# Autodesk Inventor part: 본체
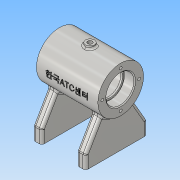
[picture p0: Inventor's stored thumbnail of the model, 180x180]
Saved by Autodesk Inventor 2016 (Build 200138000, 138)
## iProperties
Created: 2018-05
Part Number: 본체
Material: 알루미늄 6061
Document SubType Name: Modeling
Designer: Administrator
Density: 2.7 g/cm^3
Appearance: 알루미늄 - 평지
Author: Administrator
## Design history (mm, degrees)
sketch "스케치1"
  geometry: L1 (-30, 35)-(30, 35); L2 (30, 35)-(30, -35); L3 (30, -35)-(-30, -35); L4 (-30, -35)-(-30, 35); L5 (-20, 35)-(-20, -35); L6 (20, 35)-(20, -35); 3 further points
  constraints: 12 end point, 4 point on line, 3 perpendicular, 2 midpoint, 2 parallel, 1 horizontal, 1 horizontal alignment, 1 vertical alignment
  dimensions: "d0" = 60 distance of L2.end L3.end; "d1" = 70 distance of L1.end L2.end; "d2" = 10 distance between parallel lines of L5 L4; "d3" = 10 distance between parallel lines of L2 L6
extrude "돌출1" new body sketch "스케치1" distance "d4" = 15; taper "d5" = 0 deg
sketch "스케치2"
  geometry: L1 (35, 65)-(-35, 65); L2 (35, 65)-(35, 91); L3 (35, 91)-(-35, 91); L4 (-35, 91)-(-35, 65); 2 further points
  constraints: 8 end point, 2 perpendicular, 1 horizontal, 1 midpoint, 1 vertical, 1 vertical alignment
  dimensions: "d7" = 65 distance from line of point (0, 0) L1; "d8" = 70 distance of L1.start L1.end; "d9" = 52 diameter of L3 L1
revolve "회전1" sketch "스케치2" stored, may be unused: angle "d10" = 90 deg
sketch "스케치3"
  geometry: L1 (0, 0)-(-15, 0) reference; L2 (-15, 0)-(-45.614, 17.675); L3 (0, 70)-(-15, 70) reference; L4 (-15, 70)-(-45.614, 52.325); L5 (-15, 0)-(-15, 70) reference; A1 r 26 centre (-65, 35) between (-45.614, 17.675) and (-45.614, 52.325) reference; 1 further point
  constraints: 4 end point, 2 point on circle
  dimensions: "d11" = 30 deg angle of L2 L1; "d12" = 30 deg angle of L4 L3
extrude "돌출2" join sketch "스케치3" distance "d13" = 10; taper "d14" = 0 deg
sketch "스케치4"
  geometry: L1 (0, 0)-(0, 119.378); L2 (0, 65)-(35.22, -31.765); L3 (9.919, 37.749)-(15.557, 39.801); L4 (15.557, 39.801)-(14.291, 43.28); L5 (14.291, 43.28)-(8.653, 41.227); L6 (8.653, 41.227)-(9.919, 37.749)
  constraints: 12 end point, 3 perpendicular, 2 point on line, 1 vertical, 2 other
  dimensions: "d15" = 20 deg angle of L2 L1; "d16" = 6 distance of L3.start L3.end; "d17" = 29 distance from line of L3 L2.start
revolve "회전2" sketch "스케치4" stored, may be unused: angle "d18" = 90 deg
sketch "스케치5"
  geometry: L1 (0, 94)-(5, 94); L2 (5, 94)-(5, 90.515); L3 (5, 90.515)-(0, 90.515); L4 (0, 90.515)-(0, 94); 3 further points
  constraints: 8 end point, 2 parallel, 1 horizontal, 1 midpoint, 1 perpendicular, 1 vertical alignment, 2 other
  dimensions: "d19" = 10 diameter of L2 L4; "d20" = 3 dimension on L1
revolve "회전3" sketch "스케치5" stored, may be unused: angle "d21" = 90 deg
sketch "스케치6"
  geometry: L1 (35, 65)-(-35, 65); L2 (-35, 65)-(-35, 81); L3 (-35, 81)-(-23, 81); L4 (-23, 81)-(-23, 79); L5 (-23, 79)-(-21, 79); L6 (-21, 79)-(-21, 86); L7 (-21, 86)-(21, 86); L8 (21, 86)-(21, 79); L9 (21, 79)-(23, 79); L10 (23, 79)-(23, 81); L11 (23, 81)-(35, 81); L12 (35, 81)-(35, 65); L13 (35, 39)-(35, 91) reference; 1 further point
  constraints: 24 end point, 9 perpendicular, 4 point on line, 2 collinear, 1 horizontal, 1 midpoint
  dimensions: "d22" = 65 distance from line of point (0, 0) L1; "d23" = 70 distance of L1.start L1.end; "d24" = 42 distance of L6.end L7.end; "d25" = 12 distance of L10.end L11.end; "d26" = 28 diameter of L9 L1; "d27" = 32 diameter of L11 L1; "d28" = 42 diameter of L7 L1
revolve "회전4" sketch "스케치6" stored, may be unused: angle "d29" = 90 deg
hole "구멍1" diameter "d32" = 5.188; stored, may be unused: countersink angle "d36" = 90 deg, drill point angle "d38" = 118 deg; dims "d30" = 10, "d31" = 10, "d33" = 12, "d34" = 4, "d35" = 2, "d37" = 16
hole "구멍2" diameter "d41" = 5.188; stored, may be unused: countersink angle "d45" = 90 deg, drill point angle "d47" = 118 deg; dims "d39" = 10, "d40" = 10, "d42" = 12, "d43" = 4, "d44" = 2, "d46" = 16
node "작업 평면1"
sketch "스케치7"
  geometry: L1 (-35, 26)-(-35, -26) reference; L2 (35, 26)-(-35, 26) reference; 2 further points
  constraints: 1 other
  dimensions: "d48" = 35 distance from line of point (0, 0) L1; "d49" = 26 distance from line of L2 point (0, 0)
feature "엠보싱1" sketch "스케치7" dims "d0" = 60, "d1" = 70, "d2" = 10, "d3" = 10, "d50" = 0.5, "d51" = 0
sketch "스케치8" dims "d52" = 42
  geometry: C1 r 16 at (0, 0) reference; 3 further points
  constraints: 2 horizontal alignment, 1 coincident, 2 other
hole "구멍3" sketch "스케치8" at (-21, 0) diameter "d53" = 3.242; stored, may be unused: countersink angle "d57" = 90 deg, drill point angle "d59" = 118 deg; dims "d54" = 8, "d55" = 4, "d56" = 2, "d58" = 10
hole "구멍4" diameter "d65" = 4.134; stored, may be unused: countersink angle "d69" = 90 deg, drill point angle "d71" = 118 deg; dims "d63" = 5, "d64" = 15, "d66" = 8, "d67" = 4, "d68" = 2, "d70" = 10
fillet "모깎기1" dims "d78" = 3
fillet "모깎기2" dims "d79" = 3
fillet "모깎기3" dims "d80" = 3
fillet "모깎기4" dims "d81" = 2
chamfer "모따기1" distance "d82" = 1; stored, may be unused: second distance "d83" = 2, angle "d84" = 45 deg
fillet "모깎기5" dims "d87" = 0.3
sketch "스케치10"
  geometry: L1 (-97.658, 0)-(50.448, 0); L2 (50.448, 0)-(50.448, -47.248); L3 (50.448, -47.248)-(-97.658, -47.248); L4 (-97.658, -47.248)-(-97.658, 0); 1 further point
  constraints: 8 end point, 2 parallel, 1 horizontal, 1 perpendicular
extrude "돌출3" cut sketch "스케치10" stored distance "d85" = 0; taper "d86" = 0 deg
node "솔리드1"
mirror "대칭1"
pattern_circular "원형 패턴1" dims angle "d61" = 360 deg
mirror "대칭2"
pattern_linear "직사각형 패턴1" dims "d74" = 50
